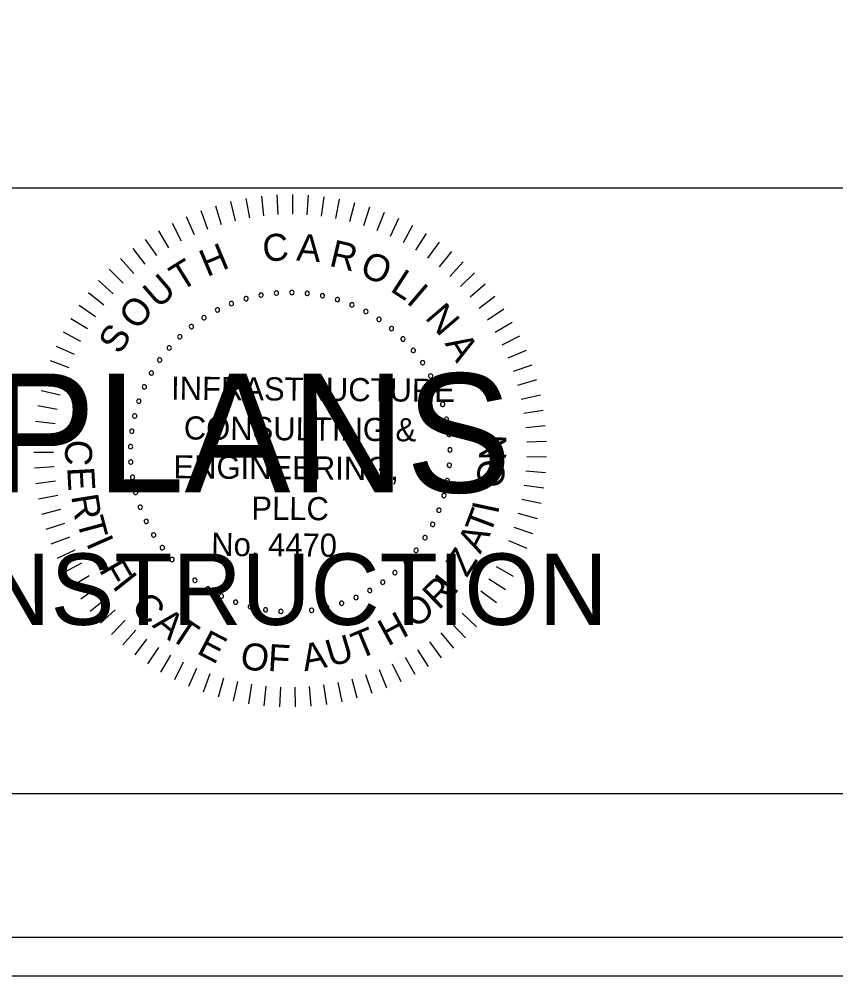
# Model space of a CAD drawing. Extents: x 967 to 1623, y 964 to 7064.
# Drawn here: x 1189.3 to 1212.88, y 3763.72 to 3791.36 of the extents above; entities that cross this region are included whole.
import ezdxf

# ---------------------------------------------------------------- set-up
doc = ezdxf.new("R2010")
doc.units = 0
for name, color, linetype in [('RD_SHT_Bndy', 7, 'Continuous'), ('RD_SHT_IplotShp', 7, 'Continuous'), ('RD_SHT_Misc1', 7, 'Continuous'), ('RD_SHT_Misc2', 7, 'Continuous'), ('RD_Sketch1', 7, 'Continuous')]:
    doc.layers.add(name, color=color, linetype=linetype)

msp = doc.modelspace()

# ---------------------------------------------------------------- linework, layer by layer
at = {"layer": 'RD_SHT_Bndy'}
for p, q in [((996.114, 3786.486), (1323.886, 3786.486)), ((1323.886, 3768.983), (996.114, 3768.983))]:
    msp.add_line(p, q, dxfattribs=at)
at = {"layer": 'RD_SHT_IplotShp'}
for points in [[(967.409, 3763.72), (1326.285, 3763.72), (1326.285, 3983.72), (967.409, 3983.72)], [(988.525, 3764.84), (1326.285, 3764.84), (1326.285, 3982.6), (988.525, 3982.6)]]:
    msp.add_lwpolyline(points, close=True, dxfattribs=at)
at = {"layer": 'RD_SHT_Misc1'}
for p, q in [((1195.846, 3786.181), (1195.945, 3785.62)), ((1196.292, 3786.245), (1196.357, 3785.68)), ((1196.742, 3786.282), (1196.772, 3785.714)), ((1197.194, 3786.292), (1197.189, 3785.723)), ((1197.645, 3786.274), (1197.606, 3785.706)), ((1198.094, 3786.228), (1198.02, 3785.664)), ((1198.54, 3786.156), (1198.432, 3785.596)), ((1194.54, 3785.827), (1194.739, 3785.293)), ((1194.968, 3785.971), (1195.134, 3785.427)), ((1195.403, 3786.09), (1195.536, 3785.536)), ((1198.98, 3786.056), (1198.838, 3785.504)), ((1199.414, 3785.929), (1199.238, 3785.387)), ((1194.122, 3785.656), (1194.353, 3785.136)), ((1199.839, 3785.777), (1199.63, 3785.246)), ((1200.253, 3785.598), (1200.013, 3785.082)), ((1193.715, 3785.461), (1193.978, 3784.956)), ((1200.656, 3785.395), (1200.385, 3784.894)), ((1192.94, 3784.997), (1193.263, 3784.528)), ((1193.321, 3785.241), (1193.614, 3784.752)), ((1201.047, 3785.167), (1200.745, 3784.684)), ((1192.576, 3784.731), (1192.926, 3784.282)), ((1201.422, 3784.917), (1201.092, 3784.453)), ((1192.228, 3784.443), (1192.605, 3784.016)), ((1201.781, 3784.643), (1201.424, 3784.2)), ((1202.124, 3784.349), (1201.739, 3783.928)), ((1191.899, 3784.134), (1192.301, 3783.731)), ((1202.447, 3784.034), (1202.038, 3783.638)), ((1191.589, 3783.805), (1192.015, 3783.428)), ((1202.751, 3783.7), (1202.318, 3783.329)), ((1191.299, 3783.459), (1191.748, 3783.108)), ((1203.034, 3783.348), (1202.579, 3783.004)), ((1191.032, 3783.095), (1191.501, 3782.772)), ((1203.294, 3782.979), (1202.82, 3782.664)), ((1190.787, 3782.716), (1191.274, 3782.422)), ((1203.532, 3782.595), (1203.04, 3782.31)), ((1190.565, 3782.323), (1191.07, 3782.059)), ((1203.746, 3782.198), (1203.237, 3781.943)), ((1190.368, 3781.916), (1190.888, 3781.684)), ((1203.936, 3781.788), (1203.412, 3781.564)), ((1190.196, 3781.499), (1190.729, 3781.299)), ((1204.1, 3781.367), (1203.563, 3781.176)), ((1190.05, 3781.072), (1190.594, 3780.905)), ((1204.238, 3780.937), (1203.691, 3780.779)), ((1189.93, 3780.636), (1190.484, 3780.503)), ((1204.349, 3780.5), (1203.794, 3780.375)), ((1189.837, 3780.195), (1190.398, 3780.095)), ((1204.434, 3780.056), (1203.872, 3779.966)), ((1189.771, 3779.748), (1190.337, 3779.683)), ((1204.491, 3779.608), (1203.925, 3779.552)), ((1189.732, 3779.298), (1190.301, 3779.267)), ((1204.522, 3779.158), (1203.953, 3779.137)), ((1189.721, 3778.847), (1190.29, 3778.851)), ((1204.524, 3778.706), (1203.955, 3778.72)), ((1189.737, 3778.396), (1190.306, 3778.434)), ((1204.499, 3778.256), (1203.932, 3778.304)), ((1189.781, 3777.946), (1190.346, 3778.019)), ((1204.447, 3777.807), (1203.884, 3777.89)), ((1189.852, 3777.5), (1190.412, 3777.608)), ((1204.367, 3777.363), (1203.81, 3777.479)), ((1189.951, 3777.06), (1190.502, 3777.201)), ((1204.261, 3776.924), (1203.712, 3777.074)), ((1190.076, 3776.626), (1190.617, 3776.8)), ((1204.128, 3776.492), (1203.589, 3776.676)), ((1190.227, 3776.2), (1190.757, 3776.408)), ((1203.969, 3776.07), (1203.442, 3776.286)), ((1190.403, 3775.785), (1190.92, 3776.024)), ((1203.784, 3775.658), (1203.271, 3775.906)), ((1190.605, 3775.381), (1191.106, 3775.651)), ((1203.574, 3775.258), (1203.078, 3775.537)), ((1190.831, 3774.99), (1191.315, 3775.291)), ((1203.341, 3774.871), (1202.862, 3775.18)), ((1191.081, 3774.614), (1191.545, 3774.943)), ((1203.085, 3774.5), (1202.626, 3774.837)), ((1191.353, 3774.253), (1191.796, 3774.61)), ((1202.806, 3774.145), (1202.368, 3774.509)), ((1191.646, 3773.91), (1192.067, 3774.293)), ((1191.96, 3773.585), (1192.356, 3773.994)), ((1202.506, 3773.807), (1202.092, 3774.197)), ((1192.293, 3773.28), (1192.664, 3773.712)), ((1202.186, 3773.488), (1201.796, 3773.903)), ((1192.644, 3772.996), (1192.988, 3773.45)), ((1201.847, 3773.19), (1201.484, 3773.628)), ((1193.011, 3772.734), (1193.327, 3773.208)), ((1201.119, 3772.657), (1200.811, 3773.136)), ((1201.491, 3772.912), (1201.155, 3773.372)), ((1193.394, 3772.495), (1193.68, 3772.987)), ((1200.731, 3772.425), (1200.453, 3772.922)), ((1193.791, 3772.279), (1194.047, 3772.788)), ((1194.2, 3772.088), (1194.424, 3772.612)), ((1199.918, 3772.034), (1199.702, 3772.561)), ((1200.331, 3772.217), (1200.083, 3772.73)), ((1194.62, 3771.923), (1194.812, 3772.459)), ((1195.05, 3771.783), (1195.208, 3772.33)), ((1199.063, 3771.745), (1198.913, 3772.295)), ((1199.495, 3771.877), (1199.312, 3772.416)), ((1195.487, 3771.67), (1195.612, 3772.225)), ((1195.93, 3771.584), (1196.021, 3772.146)), ((1196.377, 3771.524), (1196.434, 3772.091)), ((1196.828, 3771.493), (1196.85, 3772.062)), ((1197.279, 3771.488), (1197.267, 3772.058)), ((1197.73, 3771.512), (1197.683, 3772.079)), ((1198.179, 3771.562), (1198.097, 3772.126)), ((1198.624, 3771.64), (1198.508, 3772.198))]:
    msp.add_line(p, q, dxfattribs=at)
for centre, start, end in [((1195.851, 3783.285), 16.1422, 196.1422), ((1196.285, 3783.388), 10.6038, 190.6038), ((1196.285, 3783.388), 190.6038, 10.6038), ((1196.727, 3783.447), 5.0653, 185.0653), ((1196.727, 3783.447), 185.0653, 5.0653), ((1197.172, 3783.464), 359.5268, 179.5268), ((1197.172, 3783.464), 179.5268, 359.5268), ((1197.617, 3783.438), 173.9884, 353.9884), ((1197.617, 3783.438), 353.9884, 173.9884), ((1198.057, 3783.369), 168.4499, 348.4499), ((1198.057, 3783.369), 348.4499, 168.4499), ((1195.429, 3783.142), 21.6807, 201.6807), ((1195.429, 3783.142), 201.6807, 21.6807), ((1195.851, 3783.285), 196.1422, 16.1422), ((1198.489, 3783.258), 162.9114, 342.9114), ((1198.489, 3783.258), 342.9114, 162.9114), ((1198.908, 3783.106), 157.373, 337.373), ((1198.908, 3783.106), 337.373, 157.373), ((1194.637, 3782.736), 32.7576, 212.7576), ((1195.023, 3782.958), 27.2191, 207.2191), ((1195.023, 3782.958), 207.2191, 27.2191), ((1199.31, 3782.914), 151.8345, 331.8345), ((1199.31, 3782.914), 331.8345, 151.8345), ((1194.274, 3782.478), 38.2961, 218.2961), ((1194.274, 3782.478), 218.2961, 38.2961), ((1194.637, 3782.736), 212.7576, 32.7576), ((1199.692, 3782.684), 146.2961, 326.2961), ((1199.692, 3782.684), 326.2961, 146.2961), ((1193.937, 3782.186), 43.8345, 223.8345), ((1193.937, 3782.186), 223.8345, 43.8345), ((1200.05, 3782.419), 140.7576, 320.7576), ((1200.05, 3782.419), 320.7576, 140.7576), ((1200.38, 3782.12), 135.2191, 315.2191), ((1200.38, 3782.12), 315.2191, 135.2191), ((1193.63, 3781.862), 49.373, 229.373), ((1193.63, 3781.862), 229.373, 49.373), ((1200.68, 3781.79), 129.6807, 309.6807), ((1200.68, 3781.79), 309.6807, 129.6807), ((1193.356, 3781.511), 54.9114, 234.9114), ((1193.356, 3781.511), 234.9114, 54.9114), ((1200.947, 3781.433), 124.1422, 304.1422), ((1200.947, 3781.433), 304.1422, 124.1422), ((1193.117, 3781.135), 60.4499, 240.4499), ((1193.117, 3781.135), 240.4499, 60.4499), ((1201.179, 3781.052), 118.6038, 298.6038), ((1201.179, 3781.052), 298.6038, 118.6038), ((1192.915, 3780.737), 65.9884, 245.9884), ((1192.915, 3780.737), 245.9884, 65.9884), ((1201.372, 3780.651), 113.0653, 293.0653), ((1201.372, 3780.651), 293.0653, 113.0653), ((1192.753, 3780.322), 71.5268, 251.5268), ((1192.753, 3780.322), 251.5268, 71.5268), ((1201.526, 3780.233), 107.5268, 287.5268), ((1201.526, 3780.233), 287.5268, 107.5268), ((1192.632, 3779.894), 77.0653, 257.0653), ((1192.632, 3779.894), 257.0653, 77.0653), ((1201.638, 3779.801), 101.9884, 281.9884), ((1201.638, 3779.801), 281.9884, 101.9884), ((1192.552, 3779.455), 82.6038, 262.6038), ((1192.552, 3779.455), 262.6038, 82.6038), ((1201.709, 3779.361), 96.4499, 276.4499), ((1201.709, 3779.361), 276.4499, 96.4499), ((1192.515, 3779.011), 88.1422, 268.1422), ((1192.515, 3779.011), 268.1422, 88.1422), ((1201.737, 3778.917), 90.9114, 270.9114), ((1201.737, 3778.917), 270.9114, 90.9114), ((1192.522, 3778.565), 93.6807, 273.6807), ((1192.522, 3778.565), 273.6807, 93.6807), ((1201.721, 3778.471), 85.373, 265.373), ((1201.721, 3778.471), 265.373, 85.373), ((1192.571, 3778.122), 99.2191, 279.2191), ((1192.571, 3778.122), 279.2191, 99.2191), ((1201.663, 3778.029), 79.8345, 259.8345), ((1201.663, 3778.029), 259.8345, 79.8345), ((1192.662, 3777.686), 104.7576, 284.7576), ((1192.662, 3777.686), 284.7576, 104.7576), ((1201.563, 3777.595), 74.2961, 254.2961), ((1201.563, 3777.595), 254.2961, 74.2961), ((1192.796, 3777.261), 110.2961, 290.2961), ((1192.796, 3777.261), 290.2961, 110.2961), ((1201.42, 3777.173), 68.7576, 248.7576), ((1201.42, 3777.173), 248.7576, 68.7576), ((1192.97, 3776.851), 115.8345, 295.8345), ((1192.97, 3776.851), 295.8345, 115.8345), ((1201.238, 3776.766), 63.2191, 243.2191), ((1201.238, 3776.766), 243.2191, 63.2191), ((1193.182, 3776.459), 121.373, 301.373), ((1193.182, 3776.459), 301.373, 121.373), ((1201.018, 3776.379), 57.6807, 237.6807), ((1201.018, 3776.379), 237.6807, 57.6807), ((1193.432, 3776.09), 306.9114, 126.9114), ((1193.432, 3776.09), 126.9114, 306.9114), ((1200.761, 3776.014), 52.1422, 232.1422), ((1200.761, 3776.014), 232.1422, 52.1422), ((1193.715, 3775.746), 132.4499, 312.4499), ((1193.715, 3775.746), 312.4499, 132.4499), ((1200.47, 3775.677), 46.6038, 226.6038), ((1200.47, 3775.677), 226.6038, 46.6038), ((1194.031, 3775.431), 137.9884, 317.9884), ((1194.031, 3775.431), 317.9884, 137.9884), ((1200.148, 3775.369), 41.0653, 221.0653), ((1200.148, 3775.369), 221.0653, 41.0653), ((1194.376, 3775.149), 143.5268, 323.5268), ((1194.376, 3775.149), 323.5268, 143.5268), ((1199.798, 3775.093), 35.5268, 215.5268), ((1199.798, 3775.093), 215.5268, 35.5268), ((1194.746, 3774.901), 149.0653, 329.0653), ((1194.746, 3774.901), 329.0653, 149.0653), ((1199.422, 3774.853), 29.9884, 209.9884), ((1199.422, 3774.853), 209.9884, 29.9884), ((1195.139, 3774.69), 154.6038, 334.6038), ((1195.139, 3774.69), 334.6038, 154.6038), ((1195.55, 3774.517), 160.1422, 340.1422), ((1195.55, 3774.517), 340.1422, 160.1422), ((1198.611, 3774.486), 18.9114, 198.9114), ((1198.611, 3774.486), 198.9114, 18.9114), ((1199.026, 3774.65), 24.4499, 204.4499), ((1199.026, 3774.65), 204.4499, 24.4499), ((1195.975, 3774.386), 165.6807, 345.6807), ((1195.975, 3774.386), 345.6807, 165.6807), ((1196.412, 3774.295), 171.2191, 351.2191), ((1196.412, 3774.295), 351.2191, 171.2191), ((1196.855, 3774.248), 356.7576, 176.7576), ((1196.855, 3774.248), 176.7576, 356.7576), ((1197.301, 3774.243), 2.2961, 182.2961), ((1197.301, 3774.243), 182.2961, 2.2961), ((1197.745, 3774.282), 7.8345, 187.8345), ((1197.745, 3774.282), 187.8345, 7.8345), ((1198.183, 3774.363), 13.373, 193.373), ((1198.183, 3774.363), 193.373, 13.373)]:
    msp.add_arc(centre, 0.0627, start, end, dxfattribs=at)
at = {"layer": 'RD_Sketch1'}
msp.add_lwpolyline([(967.409, 3763.72), (1326.285, 3763.72), (1326.285, 3983.72), (967.409, 3983.72)], close=True, dxfattribs=at)

# ---------------------------------------------------------------- texts
at = {"layer": 'RD_SHT_Misc1'}
for s, height, rotation, p in [('C', 0.78, 4.7281, (1196.355, 3784.346)), ('A', 0.78, 355.6981, (1197.29, 3784.39)), ('H', 0.78, 22.7882, (1194.72, 3783.904)), ('R', 0.78, 346.6681, (1198.222, 3784.238)), ('T', 0.78, 31.8182, (1193.961, 3783.478)), ('O', 0.78, 337.638, (1199.096, 3783.972)), ('U', 0.78, 40.8482, (1193.306, 3782.976)), ('L', 0.78, 327.108, (1199.981, 3783.52)), ('I', 0.78, 319.578, (1200.451, 3783.182)), ('O', 0.78, 49.8782, (1192.707, 3782.341)), ('N', 0.78, 310.548, (1200.994, 3782.728)), ('S', 0.78, 58.9083, (1192.211, 3781.642)), ('A', 0.78, 301.5179, (1201.576, 3781.991)), ('INFRASTRUCTURE', 0.66873, 359.5268, (1193.682, 3780.367)), ('CONSULTING &', 0.66873, 359.5268, (1194.051, 3779.217)), ('N', 0.78, 89.2085, (1203.359, 3778.604)), ('C', 0.78, 267.025, (1190.646, 3779.227)), ('ENGINEERING,', 0.66873, 359.5268, (1193.751, 3778.095)), ('E', 0.78, 273.025, (1190.685, 3778.408)), ('O', 0.78, 83.2085, (1203.26, 3777.786)), ('R', 0.78, 279.025, (1190.799, 3777.583)), ('PLLC', 0.6687, 359.5268, (1196.002, 3776.9)), ('T', 0.78, 69.3954, (1202.891, 3776.428)), ('I', 0.78, 77.9093, (1203.121, 3777.032)), ('T', 0.78, 285.025, (1190.955, 3776.878)), ('I', 0.78, 293.7713, (1191.221, 3776.225)), ('No. 4470', 0.6687, 359.5268, (1194.843, 3775.855)), ('A', 0.78, 63.3954, (1202.616, 3775.888)), ('Z', 0.78, 57.3954, (1202.224, 3775.206)), ('F', 0.78, 299.7713, (1191.589, 3775.455)), ('I', 0.78, 308.5268, (1191.965, 3774.973)), ('I', 0.78, 52.3339, (1201.856, 3774.69)), ('R', 0.78, 44.5268, (1201.415, 3774.267)), ('C', 0.78, 314.5268, (1192.496, 3774.346)), ('O', 0.78, 38.5268, (1200.73, 3773.731)), ('A', 0.78, 320.5268, (1193.115, 3773.822)), ('H', 0.78, 28.5268, (1199.942, 3773.23)), ('T', 0.78, 326.5268, (1193.602, 3773.478)), ('E', 0.78, 332.5268, (1194.394, 3773.051)), ('T', 0.78, 22.5268, (1199.108, 3772.856)), ('U', 0.78, 16.5268, (1198.288, 3772.638)), ('O', 0.78, 350.5268, (1195.647, 3772.614)), ('F', 0.78, 356.5268, (1196.465, 3772.532)), ('A', 0.78, 10.5268, (1197.537, 3772.517))]:
    msp.add_text(s, height=height, rotation=rotation, dxfattribs=at).set_placement(p)
at = {"layer": 'RD_SHT_Misc2'}
for s, height, p in [('FINAL PLANS', 3.4375, (1174.145, 3777.685)), ('NOT FOR CONSTRUCTION', 2.0625, (1170.901, 3773.86))]:
    msp.add_text(s, height=height, dxfattribs=at).set_placement(p)

doc.saveas('drawing.dxf')
